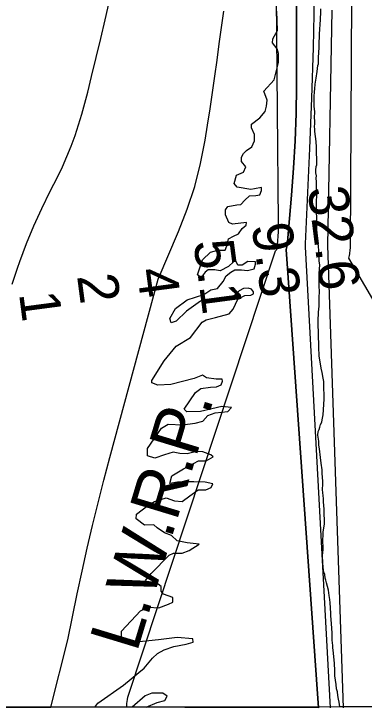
# Model space of a CAD drawing. Extents: x 3271442 to 3309282, y 752266 to 777610.
# Drawn here: x 3287356 to 3287941, y 757642 to 758801 of the extents above; entities that cross this region are included whole.
import ezdxf

# ---------------------------------------------------------------- set-up
doc = ezdxf.new("R2010")
doc.units = 0
for name, color, linetype in [('V-GRID-FRAM', 7, 'Continuous'), ('V-RIVR-EDGE', 7, 'Continuous'), ('V-RIVR-RANG', 7, 'Continuous'), ('V-SITE-VEGE', 7, 'Continuous'), ('V-TOPO-DPTH', 7, 'Continuous'), ('V-TOPO-MAJR', 7, 'Continuous'), ('V-TOPO-MINR', 7, 'Continuous'), ('V-TOPO-WATR', 7, 'Continuous'), ('V-TOPO-WATR-IDEN', 7, 'Continuous')]:
    doc.layers.add(name, color=color, linetype=linetype)

msp = doc.modelspace()

# ---------------------------------------------------------------- linework, layer by layer
at = {"layer": 'V-GRID-FRAM'}
msp.add_lwpolyline([(3275591.3, 775827.4), (3307043.5, 775836.6), (3307056.7, 757650.8), (3275588.7, 757641.7), (3275591.3, 775827.4)], dxfattribs=at)
at = {"layer": 'V-RIVR-EDGE'}
for points in [[(3287667.6, 758321.7), (3287644.5, 758305.2), (3287627.1, 758288.3), (3287618.8, 758285.3), (3287616.6, 758292.7), (3287626.2, 758309.6), (3287645.4, 758323.9), (3287659.3, 758328.2), (3287673.2, 758333), (3287685, 758340.8), (3287695.9, 758342.9), (3287705.5, 758354.6), (3287710.3, 758363.7), (3287718.1, 758369.8), (3287725.1, 758374.1), (3287735.9, 758374.1), (3287746.4, 758372.8), (3287757.2, 758375.4), (3287759.4, 758383.2), (3287759.4, 758387.5), (3287746.8, 758388), (3287737.3, 758381.5), (3287729.9, 758381.5), (3287727.3, 758387.6), (3287722.9, 758387.2), (3287714.2, 758379.4), (3287700.7, 758372.5), (3287691.6, 758373.8), (3287680.7, 758373.8), (3287675.5, 758369.9), (3287669, 758361.2), (3287662.5, 758365.6), (3287671.2, 758390.8), (3287684.7, 758403.4), (3287696.5, 758406.8), (3287709.1, 758406.8), (3287711.7, 758414.2), (3287714.3, 758425.4), (3287723, 758429.8), (3287731.3, 758433.7), (3287737, 758442.8), (3287744, 758448.4), (3287744.4, 758452.8), (3287721.4, 758449.8), (3287714.8, 758452.8), (3287709.7, 758465.4), (3287709.7, 758474.1), (3287713.2, 758479.4), (3287728.4, 758482.4), (3287735.3, 758482.8), (3287741.9, 758490.1), (3287749.3, 758497.1), (3287760.2, 758497.9), (3287766.7, 758499.2), (3287769.3, 758506.2), (3287769.3, 758511.4), (3287757.6, 758508.8), (3287751.5, 758507.9), (3287728.9, 758511.5), (3287723.7, 758518), (3287727.6, 758531.5), (3287739.4, 758536.7), (3287743.3, 758545.8), (3287736.4, 758554.5), (3287736.4, 758561.9), (3287739.5, 758568), (3287744.3, 758572.7), (3287753.4, 758578.8), (3287757.8, 758589.2), (3287757.8, 758599.6), (3287753, 758610.5), (3287753.1, 758617), (3287766.6, 758627.4), (3287775.7, 758637.9), (3287777.9, 758646.5), (3287779.2, 758656.5), (3287773.6, 758671.8), (3287790.6, 758690.8), (3287797.7, 758719.5), (3287797.7, 758734.3), (3287795.5, 758742.6), (3287787.7, 758752.1), (3287788.2, 758759.1), (3287796.5, 758773), (3287795.3, 758805.2)], [(3287605.9, 757833.2), (3287602, 757838.5), (3287602.1, 757846.3), (3287596.9, 757849.8), (3287582.1, 757849), (3287576, 757855.9), (3287585.2, 757867.6), (3287615.7, 757898), (3287622.6, 757901.5), (3287637, 757901.4), (3287648.7, 757906.2), (3287665.3, 757916.6), (3287645.7, 757918.8), (3287628.8, 757921.9), (3287619.2, 757931), (3287607.5, 757935.4), (3287595.3, 757944.1), (3287589.7, 757948.9), (3287574.1, 757948.1), (3287560.6, 757959), (3287561.1, 757966.4), (3287579.8, 757981.1), (3287591.1, 757988), (3287610.3, 757994.1), (3287624.6, 757988.8), (3287637.2, 757987.9), (3287649.8, 757997.4), (3287663.7, 758007), (3287676.4, 758006.9), (3287685.5, 758011.3), (3287688.1, 758017.3), (3287675.5, 758020), (3287656.4, 758020.5), (3287640.3, 758020.5), (3287629.4, 758020.1), (3287616.8, 758018), (3287619.9, 758030.6), (3287639.1, 758042.2), (3287664.3, 758055.7), (3287677.3, 758055.6), (3287689.1, 758062.1), (3287684.8, 758065.6), (3287671.7, 758070.4), (3287661.3, 758070.9), (3287645.6, 758067), (3287633.5, 758067.5), (3287622.2, 758069.7), (3287607.4, 758065.8), (3287591.7, 758059.8), (3287579.1, 758063.7), (3287579.2, 758075.9), (3287602.7, 758109.7), (3287613.6, 758116.6), (3287637.9, 758115.3), (3287658.8, 758118.3), (3287671.4, 758121.7), (3287680.1, 758131.3), (3287692.3, 758135.6), (3287713.2, 758137.7), (3287719.3, 758144.2), (3287703.6, 758146), (3287667.5, 758137.8), (3287644.9, 758137), (3287640.2, 758141.8), (3287659.4, 758169.6), (3287668.5, 758176.1), (3287684.6, 758178.6), (3287694.6, 758179), (3287702.4, 758182.1), (3287704.2, 758188.6), (3287703.8, 758191.6), (3287693.8, 758191.6), (3287677.7, 758193.9), (3287671.2, 758198.2), (3287657.3, 758193), (3287618.5, 758182.7), (3287596.4, 758181.4), (3287586.4, 758185.4), (3287586.4, 758189.7), (3287607.3, 758222.3), (3287627, 758246.6), (3287651.3, 758261.3), (3287670.5, 758286.5), (3287677.1, 758290.8), (3287692.7, 758294.2), (3287715.3, 758300.3), (3287722.3, 758308.1), (3287730.2, 758325), (3287741.9, 758331.1), (3287751.9, 758331.5), (3287756.3, 758334.1), (3287756.3, 758337.5), (3287752.8, 758341.9), (3287747.2, 758343.2), (3287739.3, 758342.8), (3287732.4, 758338.9), (3287726.7, 758332.8), (3287720.2, 758328.1), (3287704.5, 758323.3), (3287680.6, 758323.4), (3287667.6, 758321.7)], [(3287491.2, 757645.1), (3287496.4, 757651.8), (3287539.1, 757681.3), (3287564.8, 757702.5), (3287573.5, 757709.9), (3287587.4, 757726.8), (3287596.1, 757734.2), (3287607, 757740.2), (3287623.5, 757745.8), (3287643.6, 757750.1), (3287655.3, 757753.1), (3287654.9, 757758.8), (3287628.8, 757761), (3287597.5, 757757.2), (3287560.1, 757753.4), (3287549.2, 757755.1), (3287535.8, 757761.3), (3287535.8, 757771.3), (3287567.6, 757805.5), (3287580.7, 757811.6), (3287598.1, 757810.2), (3287614.2, 757816.7), (3287621.6, 757819.7), (3287621.6, 757827.6), (3287605.9, 757833.2)], [(3287576.9, 757645.1), (3287595.5, 757652.9), (3287608.1, 757655.9), (3287612, 757663.3), (3287604.7, 757668.1), (3287586.4, 757668.1), (3287575.5, 757663.8), (3287553.7, 757645.1)]]:
    msp.add_lwpolyline(points, dxfattribs=at)
at = {"layer": 'V-SITE-VEGE'}
for p, q in [((3287868.2, 758795.2), (3287868.8, 758800.4)), ((3287868.8, 758800.4), (3287868.7, 758808.8)), ((3287866.4, 758766.7), (3287868.2, 758791.3)), ((3287868.2, 758791.3), (3287868.2, 758795.2)), ((3287866.5, 758760.3), (3287866.4, 758766.7)), ((3287865.9, 758755.1), (3287866.5, 758760.3)), ((3287865.9, 758744.7), (3287865.9, 758755.1)), ((3287864.8, 758727.9), (3287865.9, 758744.7)), ((3287864.9, 758717.5), (3287864.8, 758727.9)), ((3287863.6, 758714.3), (3287864.9, 758717.5)), ((3287862.4, 758704.6), (3287863.6, 758714.3)), ((3287859.3, 758683.2), (3287860.5, 758693.5)), ((3287860.5, 758693.5), (3287862.4, 758704.6)), ((3287858.7, 758675.4), (3287859.3, 758683.2)), ((3287857.5, 758663.1), (3287858.1, 758670.9)), ((3287858.1, 758670.9), (3287858.7, 758675.4)), ((3287857.6, 758646.3), (3287857.5, 758663.1)), ((3287858.3, 758637.9), (3287857.6, 758646.3)), ((3287857.8, 758626.8), (3287858.3, 758637.9)), ((3287858.4, 758623), (3287857.8, 758626.8)), ((3287857.9, 758613.3), (3287858.5, 758616.5)), ((3287858.6, 758608.1), (3287857.9, 758613.3)), ((3287858.5, 758616.5), (3287858.4, 758623)), ((3287858.6, 758604.8), (3287858.6, 758608.1)), ((3287860.6, 758588), (3287858.6, 758604.8)), ((3287861.4, 758578.3), (3287860.6, 758588)), ((3287861.6, 758549.2), (3287861.4, 758578.3)), ((3287860.4, 758540.1), (3287861, 758546)), ((3287861, 758546), (3287861.6, 758549.2)), ((3287860.4, 758535.6), (3287860.4, 758540.1)), ((3287861.1, 758530.4), (3287860.4, 758535.6)), ((3287860.5, 758526.5), (3287861.1, 758530.4)), ((3287861.2, 758520.7), (3287860.5, 758526.5)), ((3287861.3, 758501.9), (3287861.2, 758520.7)), ((3287862, 758496.8), (3287861.3, 758501.9)), ((3287861.4, 758489), (3287862, 758496.8)), ((3287861.7, 758441.8), (3287861.4, 758489)), ((3287862.4, 758434.6), (3287861.7, 758441.8)), ((3287863.2, 758424.3), (3287862.4, 758434.6)), ((3287864.5, 758413.3), (3287863.2, 758424.3)), ((3287865.2, 758405.5), (3287864.5, 758413.3)), ((3287865.3, 758401), (3287865.2, 758405.5)), ((3287866, 758394.5), (3287865.3, 758401)), ((3287866, 758388.1), (3287866, 758394.5)), ((3287865.5, 758368), (3287866.7, 758382.2)), ((3287866.7, 758382.2), (3287866, 758388.1)), ((3287865.7, 758348.6), (3287865.5, 758368)), ((3287866.4, 758336.3), (3287865.7, 758348.6)), ((3287865.8, 758329.2), (3287866.4, 758336.3)), ((3287865.9, 758313.6), (3287865.8, 758329.2)), ((3287864.7, 758303.3), (3287865.9, 758313.6)), ((3287864.2, 758288.4), (3287864.7, 758303.3)), ((3287864.4, 758263.1), (3287864.2, 758288.4)), ((3287865.1, 758249.5), (3287864.4, 758263.1)), ((3287865.2, 758239.2), (3287865.1, 758249.5)), ((3287865.9, 758236), (3287865.2, 758239.2)), ((3287865.9, 758230.8), (3287865.9, 758236)), ((3287869.3, 758210.1), (3287865.9, 758230.8)), ((3287870.6, 758203), (3287869.3, 758210.1)), ((3287872.7, 758193.3), (3287870.6, 758203)), ((3287873.4, 758187.5), (3287872.7, 758193.3)), ((3287873.4, 758175.8), (3287873.4, 758187.5)), ((3287874.2, 758166.8), (3287873.4, 758175.8)), ((3287874.2, 758158.3), (3287874.2, 758166.8)), ((3287872.5, 758132.4), (3287874.2, 758158.3)), ((3287870.6, 758124), (3287872.5, 758132.4)), ((3287866.8, 758111.7), (3287868.1, 758116.2)), ((3287868.1, 758116.2), (3287870, 758120.1)), ((3287870, 758120.1), (3287870.6, 758124)), ((3287863.7, 758098.1), (3287864.3, 758104.5)), ((3287864.3, 758104.5), (3287865.5, 758107.8)), ((3287865.5, 758107.8), (3287866.8, 758111.7)), ((3287864.3, 758094.8), (3287863.7, 758098.1)), ((3287864.4, 758091.6), (3287864.3, 758094.8)), ((3287865, 758088.4), (3287864.4, 758091.6)), ((3287865.1, 758081.9), (3287865, 758088.4)), ((3287866.4, 758075.4), (3287865.1, 758081.9)), ((3287867.8, 758061.2), (3287866.4, 758075.4)), ((3287869.2, 758051.5), (3287867.8, 758061.2)), ((3287870.6, 758040.5), (3287869.2, 758051.5)), ((3287870.6, 758034.7), (3287870.6, 758040.5)), ((3287872, 758021.1), (3287870.6, 758034.7)), ((3287872.1, 758014), (3287872, 758021.1)), ((3287871.4, 758010.7), (3287872.1, 758014)), ((3287871.5, 758006.9), (3287871.4, 758010.7)), ((3287872.1, 758003), (3287871.5, 758006.9)), ((3287872.2, 757997.2), (3287872.1, 758003)), ((3287872.9, 757992.6), (3287872.2, 757997.2)), ((3287872.9, 757986.2), (3287872.9, 757992.6)), ((3287873.6, 757982.3), (3287872.9, 757986.2)), ((3287874.3, 757973.9), (3287873.6, 757982.3)), ((3287874.5, 757949.9), (3287874.3, 757973.9)), ((3287872.6, 757937), (3287874.5, 757949.9)), ((3287872.1, 757925.3), (3287872.7, 757929.8)), ((3287872.7, 757929.8), (3287872.6, 757937)), ((3287872.2, 757907.8), (3287872.1, 757925.3)), ((3287871.6, 757897.5), (3287872.2, 757907.8)), ((3287871.7, 757885.2), (3287871.6, 757897.5)), ((3287873.1, 757872.9), (3287871.7, 757885.2)), ((3287873.8, 757869.7), (3287873.1, 757872.9)), ((3287875.1, 757865.8), (3287873.8, 757869.7)), ((3287875.8, 757860), (3287875.1, 757865.8)), ((3287877.1, 757856.7), (3287875.8, 757860)), ((3287877.8, 757852.2), (3287877.1, 757856.7)), ((3287881.1, 757839.9), (3287877.8, 757852.2)), ((3287882.5, 757830.9), (3287881.1, 757839.9)), ((3287883.8, 757824.4), (3287882.5, 757830.9)), ((3287883.9, 757818.6), (3287883.8, 757824.4)), ((3287885.3, 757801.8), (3287883.9, 757818.6)), ((3287885.3, 757797.2), (3287885.3, 757801.8)), ((3287886, 757790.8), (3287885.3, 757797.2)), ((3287886.1, 757783.7), (3287886, 757790.8)), ((3287887.5, 757768.8), (3287886.1, 757783.7)), ((3287887.6, 757756.5), (3287887.5, 757768.8)), ((3287888.3, 757747.4), (3287887.6, 757756.5)), ((3287888.3, 757744.2), (3287888.3, 757747.4)), ((3287889.7, 757735.1), (3287888.3, 757744.2)), ((3287891.1, 757717.7), (3287889.7, 757735.1)), ((3287891.8, 757706), (3287891.1, 757717.7)), ((3287891.9, 757697), (3287891.8, 757706)), ((3287894, 757682.7), (3287891.9, 757697)), ((3287894.7, 757675.6), (3287894, 757682.7)), ((3287896.6, 757670.5), (3287894.7, 757675.6)), ((3287896.7, 757664.6), (3287896.6, 757670.5)), ((3287898, 757658.2), (3287896.7, 757664.6)), ((3287899.4, 757653), (3287898, 757658.2)), ((3287900.1, 757645.2), (3287899.4, 757653)), ((3288495.4, 757645.4), (3287900.1, 757645.2))]:
    msp.add_line(p, q, dxfattribs=at)
at = {"layer": 'V-TOPO-DPTH'}
for p, q in [((3287827.9, 759081.8), (3287827.8, 758679.8)), ((3287827.8, 758679.8), (3287827.2, 758634.3)), ((3287827.2, 758634.3), (3287825.8, 758588.9)), ((3287825.8, 758588.9), (3287823.2, 758543.5)), ((3287823.2, 758543.5), (3287819.8, 758498.2)), ((3287819.8, 758498.2), (3287813.1, 758420.8)), ((3287813.1, 758420.8), (3287812.1, 758414.3))]:
    msp.add_line(p, q, dxfattribs=at)
for points in [[(3287417.7, 757645.1), (3287446.6, 757757.3), (3287454.1, 757795.5), (3287462, 757833.7), (3287470.2, 757871.8), (3287478.7, 757909.8), (3287487.6, 757947.8), (3287496.8, 757985.6), (3287506.5, 758023.4), (3287516.5, 758061), (3287597, 758358.5), (3287631.1, 758437.8), (3287645.5, 758475), (3287658, 758512.7), (3287667.7, 758551.2), (3287675.4, 758590.3), (3287679.4, 758615.1), (3287683.7, 758642.2), (3287687.8, 758669.3), (3287691.6, 758696.5), (3287695.3, 758723.6), (3287698.9, 758750.8), (3287702.7, 758777.9), (3287706.6, 758805.1)], [(3287417.7, 757645.1), (3287446.6, 757757.3), (3287454.1, 757795.5), (3287462, 757833.7), (3287470.2, 757871.8), (3287478.7, 757909.8), (3287487.6, 757947.8), (3287496.8, 757985.6), (3287506.5, 758023.4), (3287516.5, 758061), (3287597, 758358.5), (3287631.1, 758437.8), (3287645.5, 758475), (3287658, 758512.7), (3287667.7, 758551.2), (3287675.4, 758590.3), (3287679.4, 758615.1), (3287683.7, 758642.2), (3287687.8, 758669.3), (3287691.6, 758696.5), (3287695.3, 758723.6), (3287698.9, 758750.8), (3287702.7, 758777.9), (3287706.6, 758805.1)], [(3287812.1, 758414.3), (3287810.7, 758407.9), (3287864.5, 757643.6), (3287417.7, 757645.1)], [(3286897.8, 757644.9), (3287417.7, 757645.1)]]:
    msp.add_lwpolyline(points, dxfattribs=at)
at = {"layer": 'V-TOPO-MAJR'}
for p, q in [((3287917.9, 758412.2), (3287921.6, 759053.6)), ((3287917.1, 758402.7), (3287917.4, 758405.1)), ((3287917.4, 758405.1), (3287917.7, 758407.5)), ((3287917.7, 758407.5), (3287917.8, 758409.8)), ((3287917.8, 758409.8), (3287917.9, 758412.2)), ((3287915.2, 758393.3), (3287915.7, 758395.7)), ((3288352.3, 757645.4), (3287915.2, 758393.3)), ((3287915.7, 758395.7), (3287916.2, 758398)), ((3287916.2, 758398), (3287916.7, 758400.4)), ((3287916.7, 758400.4), (3287917.1, 758402.7))]:
    msp.add_line(p, q, dxfattribs=at)
at = {"layer": 'V-TOPO-MINR'}
for p, q in [((3287798.1, 758452.3), (3287792.6, 759081.4)), ((3287827.8, 758679.8), (3287827.9, 759081.8)), ((3287856.3, 758744.6), (3287857.9, 758828.9)), ((3287853.7, 758660.3), (3287856.3, 758744.6)), ((3287827.2, 758634.3), (3287827.8, 758679.8)), ((3287850.4, 758576), (3287853.7, 758660.3)), ((3287825.8, 758588.9), (3287827.2, 758634.3)), ((3287823.2, 758543.5), (3287825.8, 758588.9)), ((3287843, 758417.2), (3287850.4, 758576)), ((3287819.8, 758498.2), (3287823.2, 758543.5)), ((3287813.1, 758420.8), (3287819.8, 758498.2)), ((3287798, 758444.8), (3287798.1, 758452.3)), ((3287797.9, 758437.3), (3287798, 758444.8)), ((3287796.9, 758422.4), (3287797.5, 758429.9)), ((3287797.5, 758429.9), (3287797.9, 758437.3)), ((3287795.9, 758410.8), (3287796.9, 758422.4)), ((3287812.1, 758414.3), (3287813.1, 758420.8)), ((3287547.5, 757664.9), (3287793.1, 758405.5)), ((3287793.1, 758405.5), (3287794.2, 758406.6)), ((3287794.2, 758406.6), (3287795.1, 758407.8)), ((3287795.1, 758407.8), (3287795.6, 758409.2)), ((3287795.6, 758409.2), (3287795.9, 758410.8)), ((3287546.6, 757661.5), (3287547.5, 757664.9)), ((3287545, 757650.8), (3287545.3, 757654.4)), ((3287545, 757647.2), (3287545, 757650.8)), ((3287545.3, 757654.4), (3287545.9, 757657.9)), ((3287545.9, 757657.9), (3287546.6, 757661.5)), ((3287545.2, 757645.1), (3287545, 757647.2))]:
    msp.add_line(p, q, dxfattribs=at)
for points in [[(3287353.3, 758350), (3287362.1, 758376.8), (3287366.1, 758387.7), (3287377.5, 758417.6), (3287389.7, 758447.1), (3287403, 758476.2), (3287417, 758505), (3287429, 758528.5), (3287437.2, 758545.5), (3287444.9, 758562.6), (3287451.9, 758580.1), (3287458.3, 758597.8), (3287464.2, 758615.7), (3287469.8, 758633.7), (3287474.8, 758651.9), (3287479.5, 758670.1), (3287486, 758696.4), (3287493.6, 758727.8), (3287501.2, 758759.3), (3287508.7, 758790.8), (3287516.1, 758822.3)], [(3287906.2, 757643.6), (3287880.1, 758414.7), (3287887.6, 758807)], [(3287884.7, 757643.6), (3287842.7, 758412.3), (3287843, 758417.2)], [(3287864.5, 757643.6), (3287810.7, 758407.9), (3287812.1, 758414.3)]]:
    msp.add_lwpolyline(points, dxfattribs=at)
at = {"layer": 'V-TOPO-WATR'}
msp.add_lwpolyline([(3287417.7, 757645.1), (3287446.6, 757757.3), (3287454.1, 757795.5), (3287462, 757833.7), (3287470.2, 757871.8), (3287478.7, 757909.8), (3287487.6, 757947.8), (3287496.8, 757985.6), (3287506.5, 758023.4), (3287516.5, 758061), (3287597, 758358.5), (3287631.1, 758437.8), (3287645.5, 758475), (3287658, 758512.7), (3287667.7, 758551.2), (3287675.4, 758590.3), (3287679.4, 758615.1), (3287683.7, 758642.2), (3287687.8, 758669.3), (3287691.6, 758696.5), (3287695.3, 758723.6), (3287698.9, 758750.8), (3287702.7, 758777.9), (3287706.6, 758805.1)], dxfattribs=at)

# ---------------------------------------------------------------- texts
at = {"layer": 'V-RIVR-RANG'}
for s, rotation, p in [('32.6', 277.2683, (3287846.4, 758509.8)), ('9.3', 277.5471, (3287753, 758448.6)), ('5.1', 277.5471, (3287655.8, 758420.8)), ('4', 277.5471, (3287561.2, 758373.9)), ('2', 277.5471, (3287461.6, 758363.9)), ('1', 277.5471, (3287364.7, 758334.5))]:
    msp.add_text(s, height=67, rotation=rotation, dxfattribs=at).set_placement(p)
at = {"layer": 'V-TOPO-WATR-IDEN'}
msp.add_text('L.W.R.P.', height=83, rotation=73.1156, dxfattribs=at).set_placement((3287561.4, 757734.8))

doc.saveas('drawing.dxf')
